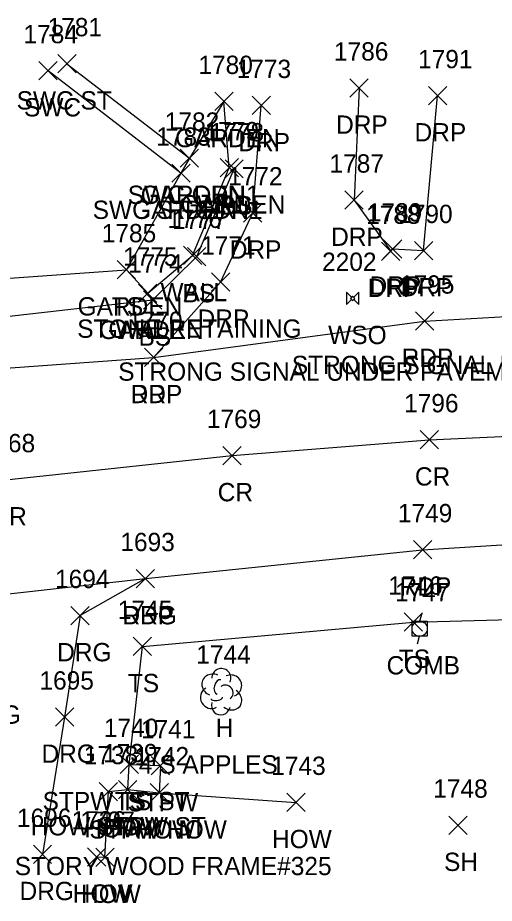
# Model space of a CAD drawing. Extents: x 1761340 to 1763889, y 696770 to 706023.
# Drawn here: x 1761917.6 to 1761969.7, y 700821 to 700917.7 of the extents above; entities that cross this region are included whole.
import ezdxf

# ---------------------------------------------------------------- set-up
doc = ezdxf.new("R2010")
doc.units = 0
for name, color, linetype in [('L_A', 7, 'Continuous'), ('L_C', 7, 'Continuous'), ('L_I', 7, 'Continuous'), ('L_TIC', 7, 'Continuous'), ('LAPB', 7, 'Continuous'), ('LBC', 7, 'Continuous'), ('LBF', 7, 'Continuous'), ('LELB', 7, 'Continuous'), ('LTD', 7, 'Continuous'), ('LW', 7, 'Continuous'), ('P_A', 7, 'Continuous'), ('P_I', 7, 'Continuous'), ('P_TIC', 7, 'Continuous'), ('PET', 7, 'Continuous'), ('PRC', 7, 'Continuous'), ('R_A', 7, 'Continuous'), ('R_I', 7, 'Continuous'), ('R_TIC', 7, 'Continuous'), ('RDG', 7, 'Continuous'), ('RDP', 7, 'Continuous'), ('RSW', 7, 'Continuous'), ('U_A', 7, 'Continuous'), ('U_C', 7, 'Continuous'), ('U_I', 7, 'Continuous'), ('UP', 7, 'Continuous'), ('UWV', 7, 'Continuous')]:
    doc.layers.add(name, color=color, linetype=linetype)

msp = doc.modelspace()

# ---------------------------------------------------------------- linework, layer by layer
at = {"layer": 'L_TIC'}
for points in [[(1761939.122, 700907.586), (1761941.122, 700909.586)], [(1761941.122, 700907.586), (1761939.122, 700909.586)], [(1761935.36, 700901.388), (1761937.36, 700903.388)], [(1761937.36, 700901.388), (1761935.36, 700903.388)], [(1761934.427, 700899.75), (1761936.427, 700901.75)], [(1761936.427, 700899.75), (1761934.427, 700901.75)], [(1761939.715, 700900.343), (1761941.715, 700902.343)], [(1761941.715, 700900.343), (1761939.715, 700902.343)], [(1761939.715, 700900.343), (1761941.715, 700902.343)], [(1761941.715, 700900.343), (1761939.715, 700902.343)], [(1761940.248, 700900.223), (1761942.248, 700902.223)], [(1761942.248, 700900.223), (1761940.248, 700902.223)], [(1761935.704, 700890.765), (1761937.704, 700892.765)], [(1761937.704, 700890.765), (1761935.704, 700892.765)], [(1761936.155, 700890.638), (1761938.155, 700892.638)], [(1761938.155, 700890.638), (1761936.155, 700892.638)], [(1761928.473, 700889.199), (1761930.473, 700891.199)], [(1761930.473, 700889.199), (1761928.473, 700891.199)], [(1761928.473, 700889.199), (1761930.473, 700891.199)], [(1761930.473, 700889.199), (1761928.473, 700891.199)], [(1761928.473, 700889.199), (1761930.473, 700891.199)], [(1761930.473, 700889.199), (1761928.473, 700891.199)], [(1761930.798, 700886.631), (1761932.798, 700888.631)], [(1761932.798, 700886.631), (1761930.798, 700888.631)], [(1761930.798, 700886.631), (1761932.798, 700888.631)], [(1761932.798, 700886.631), (1761930.798, 700888.631)], [(1761931.354, 700885.896), (1761933.354, 700887.896)], [(1761933.354, 700885.896), (1761931.354, 700887.896)], [(1761959.824, 700850.703), (1761961.824, 700852.703)], [(1761961.824, 700850.703), (1761959.824, 700852.703)], [(1761930.223, 700848.045), (1761932.223, 700850.045)], [(1761932.223, 700848.045), (1761930.223, 700850.045)], [(1761928.787, 700835.15), (1761930.787, 700837.15)], [(1761930.787, 700835.15), (1761928.787, 700837.15)], [(1761928.787, 700835.15), (1761930.787, 700837.15)], [(1761930.787, 700835.15), (1761928.787, 700837.15)], [(1761932.195, 700835.019), (1761934.195, 700837.019)], [(1761934.195, 700835.019), (1761932.195, 700837.019)], [(1761926.501, 700832.178), (1761928.501, 700834.178)], [(1761928.501, 700832.178), (1761926.501, 700834.178)], [(1761928.622, 700832.396), (1761930.622, 700834.396)], [(1761930.622, 700832.396), (1761928.622, 700834.396)], [(1761928.622, 700832.396), (1761930.622, 700834.396)], [(1761930.622, 700832.396), (1761928.622, 700834.396)], [(1761932.064, 700832.054), (1761934.064, 700834.054)], [(1761934.064, 700832.054), (1761932.064, 700834.054)], [(1761932.064, 700832.054), (1761934.064, 700834.054)], [(1761934.064, 700832.054), (1761932.064, 700834.054)], [(1761946.993, 700831.004), (1761948.993, 700833.004)], [(1761948.993, 700831.004), (1761946.993, 700833.004)], [(1761964.692, 700828.512), (1761966.692, 700830.512)], [(1761966.692, 700828.512), (1761964.692, 700830.512)], [(1761925.23, 700825.045), (1761927.23, 700827.045)], [(1761927.23, 700825.045), (1761925.23, 700827.045)], [(1761926.131, 700825.009), (1761928.131, 700827.009)], [(1761928.131, 700825.009), (1761926.131, 700827.009)]]:
    msp.add_lwpolyline(points, dxfattribs=at)
at = {"layer": 'LAPB'}
for points in [[(1761940.715, 700901.343), (1761940.122, 700908.586), (1761936.36, 700902.388), (1761935.427, 700900.75), (1761929.473, 700890.199)], [(1761931.798, 700887.631), (1761929.473, 700890.199)]]:
    msp.add_lwpolyline(points, dxfattribs=at)
at = {"layer": 'LBC'}
msp.add_lwpolyline([(1761926.23, 700826.045), (1761927.131, 700826.009), (1761927.501, 700833.178), (1761929.622, 700833.396), (1761933.064, 700833.054), (1761947.993, 700832.004)], dxfattribs=at)
at = {"layer": 'LBF'}
msp.add_lwpolyline([(1761929.622, 700833.396), (1761929.787, 700836.15), (1761933.195, 700836.019), (1761933.064, 700833.054)], dxfattribs=at)
at = {"layer": 'LELB'}
for points in [[(1761723.716, 700872.008), (1761760.57, 700872.122), (1761783.532, 700873.77), (1761799.17, 700869.892), (1761806.338, 700870.908), (1761834.789, 700874.305), (1761863.419, 700878.597), (1761884.027, 700880.868), (1761911.516, 700884.533), (1761932.354, 700886.896), (1761937.155, 700891.638), (1761941.248, 700901.223)], [(1761862.334, 700882.032), (1761883.324, 700884.689), (1761911.601, 700888.909), (1761929.473, 700890.199)], [(1761929.787, 700836.15), (1761931.223, 700849.045), (1761960.824, 700851.703), (1761987.484, 700852.436), (1762017.344, 700853.16), (1762017.87, 700847.517), (1762018.482, 700831.409)]]:
    msp.add_lwpolyline(points, dxfattribs=at)
at = {"layer": 'LTD'}
msp.add_line((1761939.802, 700844.155), (1761939.802, 700844.155), dxfattribs=at)
msp.add_line((1761939.802, 700844.155), (1761939.802, 700844.155), dxfattribs=at)
msp.add_arc((1761939.848, 700845.589), 1.047, 335.52715, 180.95627, dxfattribs=at)
for centre, major_axis, ratio, start_param, end_param in [((1761939.01, 700844.822), (1.21, -0.512), 0.895232, 1.570796, 4.712389), ((1761940.843, 700844.739), (-1.141, -0.483), 0.949671, 1.570796, 4.712389), ((1761939.593, 700844.614), (-0.208, -0.792), 0.645439, 3.141593, 6.283185), ((1761940.302, 700843.989), (-0.5, 0.667), 0.989748, 3.141593, 6.283185), ((1761938.718, 700843.447), (0.584, -1.042), 0.959034, 3.141593, 6.283185), ((1761940.802, 700843.322), (-1.09, 0.792), 0.841452, 1.570796, 4.712389), ((1761939.802, 700842.655), (0.265, 1.061), 0.942809, 1.570796, 4.712389), ((1761939.343, 700843.405), (-0.625, -0.083), 0.423636, 0, 3.141593)]:
    msp.add_ellipse(centre, major_axis=major_axis, ratio=ratio, start_param=start_param, end_param=end_param, dxfattribs=at)
at = {"layer": 'LW'}
msp.add_lwpolyline([(1761931.798, 700887.631), (1761936.704, 700891.765), (1761940.715, 700901.343)], dxfattribs=at)
at = {"layer": 'P_TIC'}
for points in [[(1761961.057, 700883.589), (1761963.057, 700885.589)], [(1761963.057, 700883.589), (1761961.057, 700885.589)], [(1761931.441, 700879.62), (1761933.441, 700881.62)], [(1761933.441, 700879.62), (1761931.441, 700881.62)], [(1761961.563, 700870.621), (1761963.563, 700872.621)], [(1761963.563, 700870.621), (1761961.563, 700872.621)], [(1761940.014, 700868.9), (1761942.014, 700870.9)], [(1761942.014, 700868.9), (1761940.014, 700870.9)], [(1761960.834, 700858.608), (1761962.834, 700860.608)], [(1761962.834, 700858.608), (1761960.834, 700860.608)], [(1761930.553, 700855.455), (1761932.553, 700857.455)], [(1761932.553, 700855.455), (1761930.553, 700857.455)]]:
    msp.add_lwpolyline(points, dxfattribs=at)
at = {"layer": 'PET'}
for points in [[(1761729.332, 700852.74), (1761740.899, 700853.176), (1761754.829, 700854.087), (1761780.546, 700856.275), (1761810.222, 700861.143), (1761821.192, 700866.007), (1761839.219, 700868.834), (1761861.11, 700872.048), (1761884.874, 700875.705), (1761913.75, 700879.268), (1761932.441, 700880.62), (1761962.057, 700884.589), (1761979.873, 700885.617), (1762011.623, 700885.448), (1762036.796, 700884.842)], [(1761729.332, 700852.74), (1761727.434, 700840.665), (1761725.471, 700828.383), (1761741.06, 700828.317), (1761766.654, 700830.86), (1761785.895, 700834.25), (1761810.857, 700839.794), (1761840.513, 700846.054), (1761863.887, 700848.795), (1761886.859, 700850.872), (1761909.086, 700853.948), (1761931.553, 700856.455), (1761961.834, 700859.608), (1761986.639, 700861.179), (1762018.608, 700861.2), (1762035.735, 700860.872)]]:
    msp.add_lwpolyline(points, dxfattribs=at)
at = {"layer": 'PRC'}
msp.add_lwpolyline([(1761727.434, 700840.665), (1761741.703, 700841.021), (1761763.595, 700842.799), (1761782.511, 700845.854), (1761809.012, 700850.746), (1761839.735, 700856.654), (1761862.596, 700860.142), (1761886.291, 700863.329), (1761916.297, 700867.259), (1761941.014, 700869.9), (1761962.563, 700871.621), (1761986.298, 700872.71), (1762008.006, 700873.289), (1762036.148, 700873.117)], dxfattribs=at)
at = {"layer": 'R_TIC'}
for points in [[(1761921.982, 700911.705), (1761923.982, 700913.705)], [(1761923.982, 700911.705), (1761921.982, 700913.705)], [(1761919.92, 700910.946), (1761921.92, 700912.946)], [(1761921.92, 700910.946), (1761919.92, 700912.946)], [(1761953.9, 700909.053), (1761955.9, 700911.053)], [(1761955.9, 700909.053), (1761953.9, 700911.053)], [(1761962.467, 700908.215), (1761964.467, 700910.215)], [(1761964.467, 700908.215), (1761962.467, 700910.215)], [(1761943.211, 700907.145), (1761945.211, 700909.145)], [(1761945.211, 700907.145), (1761943.211, 700909.145)], [(1761935.36, 700901.388), (1761937.36, 700903.388)], [(1761937.36, 700901.388), (1761935.36, 700903.388)], [(1761934.427, 700899.75), (1761936.427, 700901.75)], [(1761936.427, 700899.75), (1761934.427, 700901.75)], [(1761953.355, 700896.809), (1761955.355, 700898.809)], [(1761955.355, 700896.809), (1761953.355, 700898.809)], [(1761942.277, 700895.408), (1761944.277, 700897.408)], [(1761944.277, 700895.408), (1761942.277, 700897.408)], [(1761957.355, 700891.214), (1761959.355, 700893.214)], [(1761959.355, 700891.214), (1761957.355, 700893.214)], [(1761957.551, 700891.471), (1761959.551, 700893.471)], [(1761959.551, 700891.471), (1761957.551, 700893.471)], [(1761960.948, 700891.298), (1761962.948, 700893.298)], [(1761962.948, 700891.298), (1761960.948, 700893.298)], [(1761938.761, 700887.857), (1761940.761, 700889.857)], [(1761940.761, 700887.857), (1761938.761, 700889.857)], [(1761931.441, 700879.62), (1761933.441, 700881.62)], [(1761933.441, 700879.62), (1761931.441, 700881.62)], [(1761930.553, 700855.455), (1761932.553, 700857.455)], [(1761932.553, 700855.455), (1761930.553, 700857.455)], [(1761923.416, 700851.419), (1761925.416, 700853.419)], [(1761925.416, 700851.419), (1761923.416, 700853.419)], [(1761921.711, 700840.328), (1761923.711, 700842.328)], [(1761923.711, 700840.328), (1761921.711, 700842.328)], [(1761919.307, 700825.326), (1761921.307, 700827.326)], [(1761921.307, 700825.326), (1761919.307, 700827.326)]]:
    msp.add_lwpolyline(points, dxfattribs=at)
at = {"layer": 'RDG'}
msp.add_lwpolyline([(1761931.553, 700856.455), (1761924.416, 700852.419), (1761922.711, 700841.328), (1761920.307, 700826.326)], dxfattribs=at)
at = {"layer": 'RDP'}
for points in [[(1761954.9, 700910.053), (1761954.355, 700897.809), (1761958.355, 700892.214), (1761958.551, 700892.471), (1761961.948, 700892.298), (1761963.467, 700909.215)], [(1761932.441, 700880.62), (1761939.761, 700888.857), (1761943.277, 700896.408), (1761944.211, 700908.145)]]:
    msp.add_lwpolyline(points, dxfattribs=at)
at = {"layer": 'RSW'}
for points in [[(1761922.982, 700912.705), (1761936.36, 700902.388)], [(1761935.427, 700900.75), (1761920.92, 700911.946)]]:
    msp.add_lwpolyline(points, dxfattribs=at)
at = {"layer": 'UP'}
for p, q in [((1761961.766, 700852.649), (1761961.516, 700851.815)), ((1761960.682, 700850.149), (1761960.682, 700851.815)), ((1761960.682, 700851.815), (1761962.349, 700851.815)), ((1761962.349, 700851.815), (1761962.349, 700850.149)), ((1761961.516, 700850.982), (1761961.516, 700850.982)), ((1761962.349, 700850.149), (1761960.682, 700850.149)), ((1761961.266, 700849.315), (1761961.516, 700850.149))]:
    msp.add_line(p, q, dxfattribs=at)
msp.add_circle((1761961.516, 700850.982), 0.833, dxfattribs=at)
at = {"layer": 'UWV'}
for p, q in [((1761953.524, 700887.739), (1761954.073, 700887.19)), ((1761954.858, 700887.739), (1761954.309, 700887.19)), ((1761954.073, 700886.955), (1761953.524, 700886.406)), ((1761954.309, 700886.955), (1761954.858, 700886.406))]:
    msp.add_line(p, q, dxfattribs=at)
for points in [[(1761953.524, 700887.739), (1761953.524, 700886.406)], [(1761954.858, 700886.406), (1761954.858, 700887.739)]]:
    msp.add_lwpolyline(points, dxfattribs=at)
msp.add_lwpolyline([(1761954.427, 700887.073), (1761954.191, 700887.308), (1761953.955, 700887.073), (1761954.191, 700886.837)], close=True, dxfattribs=at)

# ---------------------------------------------------------------- texts
at = {"layer": 'L_A'}
for s, p in [('GARDEN', (1761934.791, 700903.586)), ('GARDEN', (1761931.03, 700897.388)), ('GARDEN', (1761935.384, 700896.343)), ('WALL', (1761937.203, 700896.343)), ('BS', (1761939.689, 700896.223)), ('GARDEN', (1761930.096, 700895.75)), ('WALL', (1761933.192, 700886.765)), ('BS', (1761935.596, 700886.638)), ('GARDEN', (1761924.143, 700885.199)), ('GARDEN', (1761924.143, 700885.199)), ('TS', (1761927.883, 700885.199)), ('GARDEN', (1761926.467, 700882.631)), ('WALL', (1761928.286, 700882.631)), ('BS', (1761930.795, 700881.896)), ('TS', (1761959.233, 700846.703)), ('TS', (1761929.633, 700844.045)), ('H', (1761939.235, 700839.155)), ('STPW TS ST', (1761920.314, 700831.15)), ('TS', (1761928.196, 700831.15)), ('STPW', (1761929.589, 700831.019)), ('HOW STPW ST', (1761919, 700828.396)), ('HOW', (1761924.887, 700828.178)), ('STPW HOW', (1761925.442, 700828.054)), ('HOW', (1761927.008, 700828.396)), ('HOW', (1761930.45, 700828.054)), ('HOW', (1761945.379, 700827.004)), ('SH', (1761964.18, 700824.512)), ('HOW', (1761923.616, 700821.045)), ('HOW', (1761924.517, 700821.009))]:
    msp.add_text(s, height=2, dxfattribs=at).set_placement(p)
at = {"layer": 'L_C'}
for s, p in [('STONE RETAINING', (1761924.098, 700882.765)), ('4 S APPLES', (1761930.841, 700835.155)), ('1 1/2 STORY WOOD FRAME#325', (1761910.577, 700824.054))]:
    msp.add_text(s, height=2, dxfattribs=at).set_placement(p)
at = {"layer": 'L_I'}
for s, p in [('1780', (1761937.342, 700911.586)), ('1782', (1761933.668, 700905.388)), ('1783', (1761932.734, 700903.75)), ('1779', (1761938.014, 700904.343)), ('1779', (1761938.014, 700904.343)), ('1778', (1761938.555, 700904.223)), ('1776', (1761933.956, 700894.765)), ('1777', (1761934.463, 700894.638)), ('1785', (1761926.781, 700893.199)), ('1785', (1761926.781, 700893.199)), ('1785', (1761926.781, 700893.199)), ('1775', (1761929.105, 700890.631)), ('1775', (1761929.105, 700890.631)), ('1774', (1761929.661, 700889.896)), ('1746', (1761958.076, 700854.703)), ('1745', (1761928.531, 700852.045)), ('1744', (1761937.109, 700847.155)), ('1740', (1761927.007, 700839.15)), ('1740', (1761927.007, 700839.15)), ('1741', (1761931.069, 700839.019)), ('1738', (1761924.808, 700836.178)), ('1739', (1761926.921, 700836.396)), ('1739', (1761926.921, 700836.396)), ('1742', (1761930.372, 700836.054)), ('1742', (1761930.372, 700836.054)), ('1743', (1761945.3, 700835.004)), ('1748', (1761963, 700832.512)), ('1736', (1761923.483, 700829.045)), ('1737', (1761924.438, 700829.009))]:
    msp.add_text(s, height=2, dxfattribs=at).set_placement(p)
at = {"layer": 'P_A'}
for s, p in [('RDP', (1761959.545, 700879.589)), ('RDP', (1761929.929, 700875.62)), ('CR', (1761960.996, 700866.621)), ('CR', (1761939.447, 700864.9)), ('CR', (1761914.73, 700862.259)), ('RDP', (1761959.322, 700854.608)), ('RDP', (1761929.041, 700851.455))]:
    msp.add_text(s, height=2, dxfattribs=at).set_placement(p)
at = {"layer": 'P_I'}
for s, p in [('1795', (1761959.365, 700887.589)), ('1770', (1761929.662, 700883.62)), ('1796', (1761959.815, 700874.621)), ('1769', (1761938.266, 700872.9)), ('1768', (1761913.557, 700870.259)), ('1749', (1761959.133, 700862.608)), ('1693', (1761928.813, 700859.455))]:
    msp.add_text(s, height=2, dxfattribs=at).set_placement(p)
at = {"layer": 'R_A'}
for s, p in [('SWC ST', (1761917.478, 700907.705)), ('SWC', (1761918.282, 700906.946)), ('DRP', (1761952.388, 700905.053)), ('DRP', (1761960.955, 700904.215)), ('DRP', (1761941.699, 700903.145)), ('SWC GDN1', (1761929.62, 700897.388)), ('SWC ST GDN1', (1761925.789, 700895.75)), ('DRP', (1761951.843, 700892.809)), ('DRP', (1761940.765, 700891.408)), ('DRP', (1761955.843, 700887.214)), ('DRP', (1761956.039, 700887.471)), ('DRP', (1761959.437, 700887.298)), ('DRP', (1761937.249, 700883.857)), ('DRP', (1761929.929, 700875.62)), ('DRG', (1761929.041, 700851.455)), ('DRG', (1761921.904, 700847.419)), ('DRG', (1761911.989, 700840.601)), ('DRG', (1761920.199, 700836.328)), ('DRG', (1761917.795, 700821.326))]:
    msp.add_text(s, height=2, dxfattribs=at).set_placement(p)
at = {"layer": 'R_I'}
for s, p in [('1781', (1761920.856, 700915.705)), ('1784', (1761918.227, 700914.946)), ('1786', (1761952.152, 700913.053)), ('1791', (1761961.341, 700912.215)), ('1773', (1761941.519, 700911.145)), ('1782', (1761933.668, 700905.388)), ('1783', (1761932.734, 700903.75)), ('1787', (1761951.662, 700900.809)), ('1772', (1761940.584, 700899.408)), ('1788', (1761955.663, 700895.214)), ('1789', (1761955.85, 700895.471)), ('1790', (1761959.169, 700895.298)), ('1771', (1761937.635, 700891.857)), ('1770', (1761929.662, 700883.62)), ('1693', (1761928.813, 700859.455)), ('1694', (1761921.676, 700855.419)), ('1695', (1761919.971, 700844.328)), ('1696', (1761917.512, 700829.326))]:
    msp.add_text(s, height=2, dxfattribs=at).set_placement(p)
at = {"layer": 'U_A'}
for s, p in [('WSO', (1761951.522, 700882.073)), ('COMB', (1761957.901, 700845.982))]:
    msp.add_text(s, height=2, dxfattribs=at).set_placement(p)
at = {"layer": 'U_C'}
for p in [(1761947.551, 700878.796), (1761928.577, 700878.073)]:
    msp.add_text('STRONG SIGNAL UNDER PAVEMENT', height=2, dxfattribs=at).set_placement(p)
at = {"layer": 'U_I'}
for s, p in [('2202', (1761950.853, 700890.073)), ('1747', (1761958.823, 700853.982))]:
    msp.add_text(s, height=2, dxfattribs=at).set_placement(p)

doc.saveas('drawing.dxf')
